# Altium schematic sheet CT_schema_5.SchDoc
size 136 x 123 mm
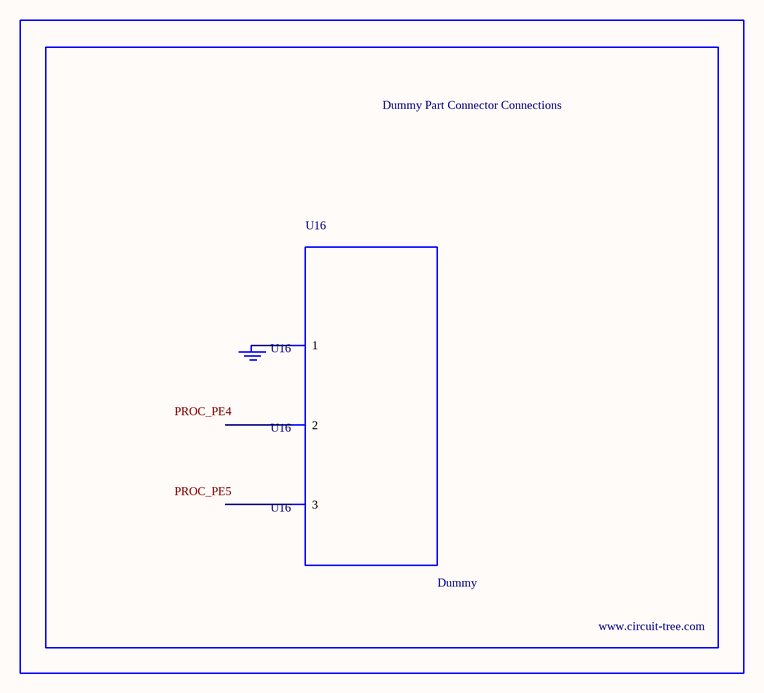
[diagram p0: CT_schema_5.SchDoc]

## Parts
BORDER4  (no value)
GND_INSTANCE_4_0  (no value)
U16  Dummy  [DUMMY_PACKAGE_138]

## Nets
NetGND_INSTANCE_4_0_0: GND_INSTANCE_4_0.0(GND) U16.1

Not connected (* = marked no-connect by the designer): U16 2 3

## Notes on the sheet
- Labels drawn without touching a wire or pin: PROC_PE4, PROC_PE5

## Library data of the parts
BORDER4 = BORDER_PAGE4
GND_INSTANCE_4_0 = GND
